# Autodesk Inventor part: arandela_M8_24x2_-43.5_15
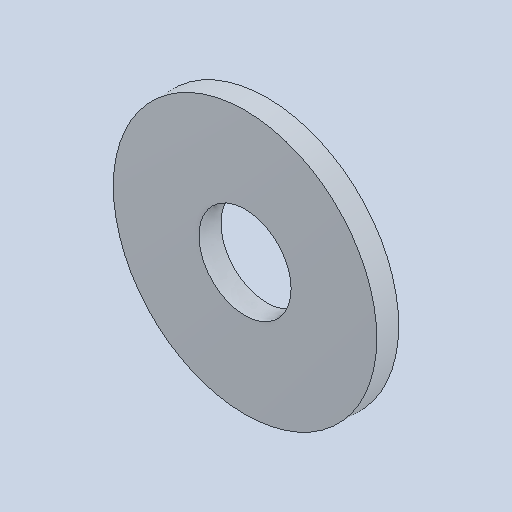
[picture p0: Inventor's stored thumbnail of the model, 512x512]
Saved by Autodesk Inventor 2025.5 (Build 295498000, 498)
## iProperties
Created: 2026-10
Part Number: arandela_M8_24x2_-43.5_15
Material: Genérico
Document SubType Name: Modeling
Designer: Luis M
Density: 1 g/cm^3
Appearance: Valor por defecto
Author: Luis M
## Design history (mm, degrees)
feature "Base1"
node "Sólido1"
